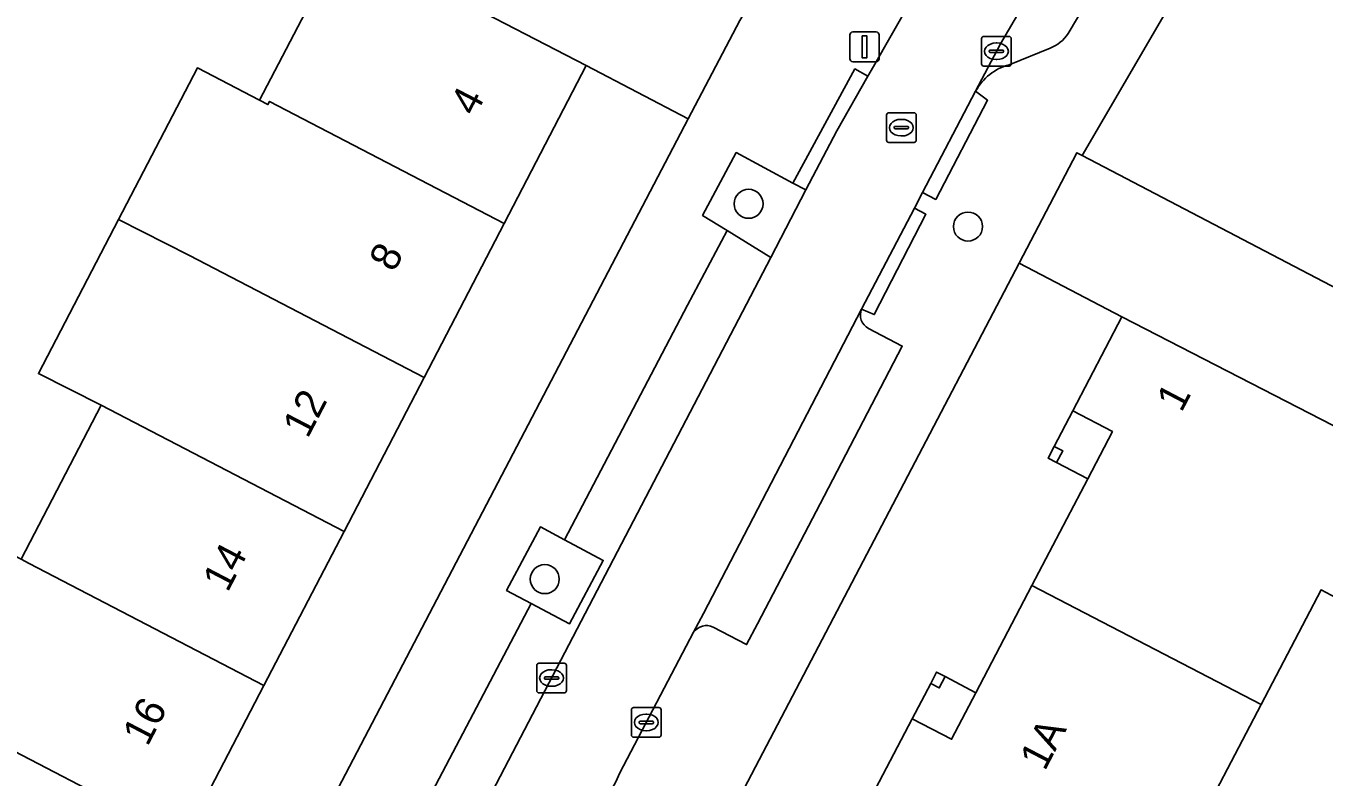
# Model space of a CAD drawing. Extents: x 160349 to 161355, y 381727 to 382854.
# Drawn here: x 160793.05 to 160836.79, y 382084.42 to 382109.72 of the extents above; entities that cross this region are included whole.
import ezdxf

# ---------------------------------------------------------------- set-up
doc = ezdxf.new("R2010")
doc.units = 0
for name, color, linetype in [('IMGEO_Boom', 7, 'Continuous'), ('IMGEO_Erf', 7, 'Continuous'), ('IMGEO_Groenvoorziening', 7, 'Continuous'), ('IMGEO_Kolk', 7, 'Continuous'), ('IMGEO_Lichtmast', 7, 'Continuous'), ('IMGEO_Muur', 7, 'Continuous'), ('IMGEO_Pand', 7, 'Continuous'), ('IMGEO_Pand_nummerreeks', 7, 'Continuous'), ('IMGEO_Pand_overbouw', 7, 'Continuous'), ('IMGEO_Parkeervlak_open', 7, 'Continuous'), ('IMGEO_Rijbaan_lokaal_open', 7, 'Continuous'), ('IMGEO_Rioolput', 7, 'Continuous'), ('IMGEO_Voetpad_halfverhard', 7, 'Continuous'), ('IMGEO_Voetpad_open', 7, 'Continuous')]:
    doc.layers.add(name, color=color, linetype=linetype)

msp = doc.modelspace()

# ---------------------------------------------------------------- linework, layer by layer
at = {"layer": 'IMGEO_Boom'}
for centre in [(160817.404, 382103.73), (160824.796, 382102.962), (160810.535, 382091.084)]:
    msp.add_circle(centre, 0.489, dxfattribs=at)
at = {"layer": 'IMGEO_Erf'}
for points in [[(160842.749, 382129.543), (160835.677, 382117.417), (160828.644, 382105.359), (160839.235, 382099.82)], [(160770.681, 382054.01), (160771.973, 382056.494), (160774.003, 382055.443), (160776.698, 382060.627), (160777.987, 382063.105), (160775.898, 382064.191), (160777.308, 382066.904), (160779.397, 382065.817), (160782.089, 382070.994), (160783.303, 382073.329), (160781.132, 382074.476), (160782.626, 382077.35), (160785.319, 382082.53), (160787.492, 382081.384), (160790.191, 382086.575), (160788.349, 382087.527), (160791.046, 382092.715), (160792.886, 382091.758), (160795.583, 382096.945), (160793.473, 382098.009), (160796.174, 382103.204), (160798.829, 382108.309), (160800.926, 382107.218), (160803.747, 382112.644)], [(160785.858, 382050.188), (160815.372, 382106.589), (160811.933, 382108.388), (160809.166, 382103.067), (160806.468, 382097.879), (160803.77, 382092.691), (160801.072, 382087.502), (160798.374, 382082.314), (160795.676, 382077.125), (160792.978, 382071.937), (160790.28, 382066.748), (160787.582, 382061.561), (160784.884, 382056.371), (160782.186, 382051.184)], [(160807.837, 382054.259), (160809.727, 382057.872), (160811.811, 382061.857), (160812.433, 382063.047), (160811.083, 382063.753), (160812.701, 382066.846), (160814.29, 382069.884), (160815.647, 382069.175), (160816.477, 382070.761), (160818.349, 382074.341), (160820.249, 382077.974), (160821.058, 382079.522), (160819.702, 382080.232), (160821.314, 382083.315), (160822.918, 382086.381), (160824.243, 382085.688), (160825.065, 382087.259), (160826.953, 382090.869), (160828.832, 382094.462), (160829.665, 382096.055), (160828.329, 382096.753), (160829.984, 382099.917), (160826.52, 382101.729), (160800.981, 382052.95)], [(160837.714, 382090.187), (160836.694, 382090.72), (160834.676, 382086.862), (160832.655, 382082.997), (160833.72, 382082.44), (160837.592, 382080.403), (160835.263, 382075.977), (160831.402, 382078.008), (160829.132, 382073.668), (160831.791, 382072.269), (160829.768, 382068.424), (160826.069, 382070.37), (160824.05, 382066.51), (160825.096, 382065.963), (160822.794, 382061.562), (160820.506, 382057.187), (160819.452, 382057.738), (160817.44, 382053.89)]]:
    msp.add_lwpolyline(points, dxfattribs=at)
for points in [[(160827.703, 382095.556), (160827.987, 382095.407), (160827.78, 382095.012), (160827.496, 382095.16)], [(160823.54, 382087.57), (160823.739, 382087.95), (160824.025, 382087.8), (160823.826, 382087.42)]]:
    msp.add_lwpolyline(points, close=True, dxfattribs=at)
at = {"layer": 'IMGEO_Groenvoorziening'}
for points in [[(160819.334, 382104.195), (160818.896, 382104.43), (160816.986, 382105.454), (160815.852, 382103.339), (160816.678, 382102.83), (160818.149, 382101.922)], [(160812.507, 382091.714), (160811.199, 382092.411), (160810.389, 382092.843), (160809.248, 382090.703), (160810.072, 382090.264), (160811.366, 382089.574)]]:
    msp.add_lwpolyline(points, close=True, dxfattribs=at)
at = {"layer": 'IMGEO_Kolk'}
for p, q in [((160825.255, 382108.442), (160825.255, 382109.294)), ((160825.33, 382109.368), (160826.182, 382109.368)), ((160825.743, 382109.148), (160825.768, 382109.148)), ((160826.256, 382109.294), (160826.256, 382108.442)), ((160825.514, 382108.862), (160825.514, 382108.874)), ((160825.952, 382108.825), (160825.554, 382108.825)), ((160825.557, 382108.911), (160825.955, 382108.911)), ((160825.998, 382108.874), (160825.998, 382108.862)), ((160826.182, 382108.368), (160825.33, 382108.368)), ((160825.766, 382108.588), (160825.741, 382108.588)), ((160810.262, 382087.327), (160810.262, 382088.179)), ((160810.337, 382088.253), (160811.189, 382088.253)), ((160811.263, 382088.179), (160811.263, 382087.327)), ((160810.521, 382087.747), (160810.521, 382087.759)), ((160810.959, 382087.71), (160810.561, 382087.71)), ((160810.564, 382087.796), (160810.962, 382087.796)), ((160810.75, 382088.033), (160810.775, 382088.033)), ((160811.005, 382087.759), (160811.005, 382087.747)), ((160811.189, 382087.253), (160810.337, 382087.253)), ((160810.773, 382087.473), (160810.748, 382087.473)), ((160813.455, 382085.831), (160813.455, 382086.683)), ((160813.53, 382086.757), (160814.382, 382086.757)), ((160813.943, 382086.537), (160813.968, 382086.537)), ((160814.456, 382086.683), (160814.456, 382085.831)), ((160813.714, 382086.251), (160813.714, 382086.263)), ((160814.152, 382086.214), (160813.754, 382086.214)), ((160813.757, 382086.3), (160814.155, 382086.3)), ((160813.966, 382085.977), (160813.941, 382085.977)), ((160814.198, 382086.263), (160814.198, 382086.251)), ((160814.382, 382085.757), (160813.53, 382085.757))]:
    msp.add_line(p, q, dxfattribs=at)
for points in [[(160825.255, 382108.442), (160825.255, 382109.294)], [(160825.33, 382109.368), (160826.182, 382109.368)], [(160826.256, 382109.294), (160826.256, 382108.442)], [(160826.182, 382108.368), (160825.33, 382108.368)], [(160810.262, 382087.327), (160810.262, 382088.179)], [(160810.337, 382088.253), (160811.189, 382088.253)], [(160811.263, 382088.179), (160811.263, 382087.327)], [(160811.189, 382087.253), (160810.337, 382087.253)], [(160813.455, 382085.831), (160813.455, 382086.683)], [(160813.53, 382086.757), (160814.382, 382086.757)], [(160814.456, 382086.683), (160814.456, 382085.831)], [(160814.382, 382085.757), (160813.53, 382085.757)]]:
    msp.add_lwpolyline(points, dxfattribs=at)
for centre, radius, start, end in [((160825.332, 382109.292), 0.0765, 91.552, 178.448), ((160825.332, 382109.292), 0.0765, 91.552, 178.448), ((160826.18, 382109.292), 0.0765, 1.552, 88.448), ((160826.18, 382109.292), 0.0765, 1.552, 88.448), ((160825.554, 382108.871), 0.0403, 85.8775, 175.7526), ((160825.551, 382108.861), 0.0366, 178.938, 274.7102), ((160825.955, 382108.868), 0.043, 264.8664, 352.4533), ((160825.959, 382108.873), 0.0386, 1.7309, 96.639), ((160825.332, 382108.444), 0.0765, 181.552, 268.448), ((160825.332, 382108.444), 0.0765, 181.552, 268.448), ((160826.18, 382108.444), 0.0765, 271.552, 358.448), ((160826.18, 382108.444), 0.0765, 271.552, 358.448), ((160810.339, 382088.177), 0.0765, 91.552, 178.448), ((160810.339, 382088.177), 0.0765, 91.552, 178.448), ((160811.187, 382088.177), 0.0765, 1.552, 88.448), ((160811.187, 382088.177), 0.0765, 1.552, 88.448), ((160810.561, 382087.756), 0.0403, 85.8775, 175.7526), ((160810.558, 382087.746), 0.0366, 178.938, 274.7102), ((160810.962, 382087.753), 0.043, 264.8664, 352.4533), ((160810.966, 382087.758), 0.0386, 1.7309, 96.639), ((160810.339, 382087.329), 0.0765, 181.552, 268.448), ((160810.339, 382087.329), 0.0765, 181.552, 268.448), ((160811.187, 382087.329), 0.0765, 271.552, 358.448), ((160811.187, 382087.329), 0.0765, 271.552, 358.448), ((160813.532, 382086.681), 0.0765, 91.552, 178.448), ((160813.532, 382086.681), 0.0765, 91.552, 178.448), ((160814.38, 382086.681), 0.0765, 1.552, 88.448), ((160814.38, 382086.681), 0.0765, 1.552, 88.448), ((160813.754, 382086.26), 0.0403, 85.8775, 175.7526), ((160813.751, 382086.25), 0.0366, 178.938, 274.7102), ((160814.155, 382086.257), 0.043, 264.8664, 352.4533), ((160814.159, 382086.262), 0.0386, 1.7309, 96.639), ((160813.532, 382085.833), 0.0765, 181.552, 268.448), ((160813.532, 382085.833), 0.0765, 181.552, 268.448), ((160814.38, 382085.833), 0.0765, 271.552, 358.448), ((160814.38, 382085.833), 0.0765, 271.552, 358.448)]:
    msp.add_arc(centre, radius, start, end, dxfattribs=at)
for centre, major_axis, ratio, start_param, end_param in [((160825.742, 382108.868), (-0.387, 0.002), 0.722429, 4.712389, 7.853982), ((160825.767, 382108.868), (-0.39, 0.002), 0.717154, 1.570796, 4.712389), ((160810.749, 382087.753), (-0.387, 0.002), 0.722429, 4.712389, 7.853982), ((160810.774, 382087.753), (-0.39, 0.002), 0.717154, 1.570796, 4.712389), ((160813.942, 382086.257), (-0.387, 0.002), 0.722429, 4.712389, 7.853982), ((160813.967, 382086.257), (-0.39, 0.002), 0.717154, 1.570796, 4.712389)]:
    msp.add_ellipse(centre, major_axis=major_axis, ratio=ratio, start_param=start_param, end_param=end_param, dxfattribs=at)
at = {"layer": 'IMGEO_Lichtmast'}
for p, q in [((160820.914, 382109.518), (160821.704, 382109.518)), ((160821.704, 382109.518), (160820.914, 382109.518)), ((160820.814, 382108.618), (160820.814, 382109.418)), ((160820.814, 382109.418), (160820.814, 382108.618)), ((160821.804, 382109.418), (160821.804, 382108.618)), ((160821.804, 382108.618), (160821.804, 382109.418)), ((160821.704, 382108.518), (160820.914, 382108.518)), ((160820.914, 382108.518), (160821.704, 382108.518))]:
    msp.add_line(p, q, dxfattribs=at)
msp.add_lwpolyline([(160821.234, 382109.393), (160821.384, 382109.393), (160821.384, 382108.643), (160821.234, 382108.643), (160821.234, 382109.393)], dxfattribs=at)
for centre, start, end in [((160820.914, 382109.418), 90, 180), ((160820.914, 382109.418), 90, 180), ((160821.704, 382109.418), 0, 90), ((160821.704, 382109.418), 360, 90), ((160820.914, 382108.618), 180, 270), ((160820.914, 382108.618), 180, 270), ((160821.704, 382108.618), 270, 0), ((160821.704, 382108.618), 270, 0)]:
    msp.add_arc(centre, 0.1, start, end, dxfattribs=at)
at = {"layer": 'IMGEO_Muur'}
msp.add_lwpolyline([(160828.644, 382105.359), (160835.677, 382117.417)], dxfattribs=at)
at = {"layer": 'IMGEO_Pand'}
for points in [[(160809.166, 382103.067), (160811.933, 382108.388), (160807.497, 382110.694), (160803.747, 382112.644), (160800.926, 382107.218), (160801.205, 382107.073), (160801.26, 382107.178)], [(160809.166, 382103.067), (160801.26, 382107.178), (160801.205, 382107.073), (160800.926, 382107.218), (160798.829, 382108.309), (160796.174, 382103.204), (160798.562, 382101.991), (160806.468, 382097.879)], [(160828.644, 382105.359), (160828.467, 382105.452), (160826.52, 382101.729), (160829.984, 382099.917), (160837.1, 382096.26), (160839.235, 382099.82)], [(160806.468, 382097.879), (160798.562, 382101.991), (160796.174, 382103.204), (160793.473, 382098.009), (160795.583, 382096.945), (160795.864, 382096.803), (160803.77, 382092.691)], [(160840.049, 382094.652), (160837.1, 382096.26), (160829.984, 382099.917), (160828.329, 382096.753), (160829.665, 382096.055), (160828.832, 382094.462), (160826.953, 382090.869), (160834.676, 382086.862), (160836.694, 382090.72), (160837.714, 382090.187)], [(160792.886, 382091.758), (160793.165, 382091.614), (160801.072, 382087.502), (160803.77, 382092.691), (160795.864, 382096.803), (160795.583, 382096.945)], [(160827.987, 382095.407), (160827.703, 382095.556), (160827.496, 382095.16), (160827.78, 382095.012)], [(160801.072, 382087.502), (160793.165, 382091.614), (160792.886, 382091.758), (160791.046, 382092.715), (160788.349, 382087.527), (160790.191, 382086.575), (160790.467, 382086.426), (160798.374, 382082.314)], [(160826.953, 382090.869), (160825.065, 382087.259), (160824.243, 382085.688), (160822.918, 382086.381), (160821.314, 382083.315), (160831.402, 382078.008), (160835.263, 382075.977), (160837.592, 382080.403), (160833.72, 382082.44), (160832.655, 382082.997), (160834.676, 382086.862)], [(160823.54, 382087.57), (160823.826, 382087.42), (160824.025, 382087.8), (160823.739, 382087.95)], [(160795.676, 382077.125), (160798.374, 382082.314), (160790.467, 382086.426), (160790.191, 382086.575), (160787.492, 382081.384), (160787.768, 382081.238)]]:
    msp.add_lwpolyline(points, close=True, dxfattribs=at)
at = {"layer": 'IMGEO_Pand_overbouw'}
for points in [[(160829.665, 382096.055), (160828.329, 382096.753), (160827.703, 382095.556), (160827.987, 382095.407), (160827.78, 382095.012), (160828.832, 382094.462)], [(160825.065, 382087.259), (160824.025, 382087.8), (160823.826, 382087.42), (160823.54, 382087.57), (160822.918, 382086.381), (160824.243, 382085.688)]]:
    msp.add_lwpolyline(points, close=True, dxfattribs=at)
at = {"layer": 'IMGEO_Parkeervlak_open'}
for points in [[(160830.73, 382117.391), (160825.888, 382109.122), (160825.053, 382107.525)], [(160828.175, 382109.465), (160830.969, 382114.176)], [(160826.185, 382108.417), (160827.56, 382108.973)], [(160821.211, 382100.185), (160815.882, 382089.93), (160815.548, 382089.292)], [(160822.583, 382098.937), (160821.446, 382099.527)], [(160816.208, 382089.468), (160817.337, 382088.882), (160817.7, 382089.575), (160819.954, 382093.882), (160822.583, 382098.937)]]:
    msp.add_lwpolyline(points, dxfattribs=at)
msp.add_lwpolyline([(160808.496, 382083.401), (160818.149, 382101.922), (160816.678, 382102.83), (160815.347, 382100.318), (160811.199, 382092.411), (160812.507, 382091.714), (160811.366, 382089.574), (160810.072, 382090.264), (160806.06, 382082.618), (160800.949, 382072.885), (160802.295, 382072.181), (160801.183, 382070.054), (160799.833, 382070.76), (160796.773, 382064.931), (160794.848, 382061.235), (160796.305, 382060.431), (160795.225, 382058.478), (160793.818, 382059.258), (160786.33, 382044.882), (160786.132, 382044.532), (160787.675, 382043.693), (160790.333, 382048.763), (160791.683, 382051.339), (160794.187, 382056.116)], close=True, dxfattribs=at)
for centre, radius, start, end in [((160827.1, 382110.179), 1.291, 290.8978, 326.4218), ((160826.68, 382106.624), 1.86, 105.446, 151.0292), ((160821.682, 382099.982), 0.513, 156.7068, 242.6008), ((160815.982, 382088.991), 0.528, 64.6138, 145.249)]:
    msp.add_arc(centre, radius, start, end, dxfattribs=at)
at = {"layer": 'IMGEO_Rijbaan_lokaal_open'}
for points in [[(160795.072, 382050.062), (160798.583, 382056.787), (160804.319, 382067.782), (160807.108, 382073.197), (160807.247, 382073.463), (160812.87, 382084.152), (160812.927, 382084.26), (160813.067, 382084.559), (160815.548, 382089.292), (160815.882, 382089.93), (160821.211, 382100.185), (160822.991, 382103.583), (160823.266, 382104.109), (160825.053, 382107.525), (160825.888, 382109.122), (160830.73, 382117.391)], [(160822.844, 382110.527), (160821.61, 382108.36), (160821.424, 382108.034), (160820.371, 382106.185), (160819.334, 382104.195), (160818.149, 382101.922), (160808.496, 382083.401), (160794.187, 382056.116), (160791.683, 382051.339)]]:
    msp.add_lwpolyline(points, dxfattribs=at)
at = {"layer": 'IMGEO_Rioolput'}
for p, q in [((160822.05, 382105.869), (160822.05, 382106.721)), ((160822.125, 382106.795), (160822.977, 382106.795)), ((160822.538, 382106.575), (160822.563, 382106.575)), ((160823.051, 382106.721), (160823.051, 382105.869)), ((160822.309, 382106.289), (160822.309, 382106.301)), ((160822.747, 382106.252), (160822.349, 382106.252)), ((160822.352, 382106.338), (160822.75, 382106.338)), ((160822.561, 382106.015), (160822.536, 382106.015)), ((160822.793, 382106.301), (160822.793, 382106.289)), ((160822.977, 382105.795), (160822.125, 382105.795))]:
    msp.add_line(p, q, dxfattribs=at)
for points in [[(160822.05, 382105.869), (160822.05, 382106.721)], [(160822.125, 382106.795), (160822.977, 382106.795)], [(160823.051, 382106.721), (160823.051, 382105.869)], [(160822.977, 382105.795), (160822.125, 382105.795)]]:
    msp.add_lwpolyline(points, dxfattribs=at)
for centre, radius, start, end in [((160822.127, 382106.719), 0.0765, 91.552, 178.448), ((160822.127, 382106.719), 0.0765, 91.552, 178.448), ((160822.975, 382106.719), 0.0765, 1.552, 88.448), ((160822.975, 382106.719), 0.0765, 1.552, 88.448), ((160822.349, 382106.298), 0.0403, 85.8775, 175.7526), ((160822.346, 382106.288), 0.0366, 178.938, 274.7102), ((160822.75, 382106.295), 0.043, 264.8664, 352.4533), ((160822.754, 382106.3), 0.0386, 1.7309, 96.639), ((160822.127, 382105.871), 0.0765, 181.552, 268.448), ((160822.127, 382105.871), 0.0765, 181.552, 268.448), ((160822.975, 382105.871), 0.0765, 271.552, 358.448), ((160822.975, 382105.871), 0.0765, 271.552, 358.448)]:
    msp.add_arc(centre, radius, start, end, dxfattribs=at)
for centre, major_axis, ratio, start_param, end_param in [((160822.537, 382106.295), (-0.387, 0.002), 0.722429, 4.712389, 7.853982), ((160822.562, 382106.295), (-0.39, 0.002), 0.717154, 1.570796, 4.712389)]:
    msp.add_ellipse(centre, major_axis=major_axis, ratio=ratio, start_param=start_param, end_param=end_param, dxfattribs=at)
at = {"layer": 'IMGEO_Voetpad_halfverhard'}
msp.add_lwpolyline([(160807.497, 382110.694), (160811.933, 382108.388), (160815.372, 382106.589), (160817.107, 382109.905)], dxfattribs=at)
at = {"layer": 'IMGEO_Voetpad_open'}
for points in [[(160830.101, 382132.01), (160817.137, 382109.957), (160817.107, 382109.905), (160815.372, 382106.589), (160785.858, 382050.188), (160759.835, 382000), (160751.631, 381984.178), (160750, 381983.553), (160754.728, 381981.086)], [(160826.52, 382101.729), (160828.467, 382105.452), (160828.644, 382105.359), (160835.677, 382117.417), (160842.749, 382129.543), (160839.149, 382131.333)], [(160830.969, 382114.176), (160828.175, 382109.465)], [(160786.33, 382044.882), (160793.818, 382059.258), (160793.126, 382059.641), (160794.204, 382061.59), (160794.848, 382061.235), (160796.773, 382064.931), (160799.833, 382070.76), (160799.056, 382071.166), (160800.168, 382073.293), (160800.949, 382072.885), (160806.06, 382082.618), (160810.072, 382090.264), (160809.248, 382090.703), (160810.389, 382092.843), (160811.199, 382092.411), (160815.347, 382100.318), (160816.678, 382102.83), (160815.852, 382103.339), (160816.986, 382105.454), (160818.896, 382104.43), (160820.985, 382108.272), (160821.424, 382108.034), (160821.61, 382108.36), (160822.844, 382110.527)], [(160827.56, 382108.973), (160826.185, 382108.417)], [(160825.053, 382107.525), (160825.456, 382107.217), (160823.709, 382103.877), (160823.266, 382104.109), (160822.991, 382103.583), (160823.38, 382103.379), (160821.639, 382100), (160821.211, 382100.185)], [(160758.807, 381979.11), (160762.776, 381976.768), (160762.232, 381978.206), (160773.531, 382000), (160800.003, 382051.064), (160800.514, 382052.05), (160800.981, 382052.95), (160826.52, 382101.729)], [(160821.446, 382099.527), (160822.583, 382098.937), (160819.954, 382093.882), (160817.7, 382089.575), (160817.337, 382088.882), (160816.208, 382089.468)], [(160815.548, 382089.292), (160813.067, 382084.559), (160812.927, 382084.26), (160812.87, 382084.152)]]:
    msp.add_lwpolyline(points, dxfattribs=at)
for points in [[(160820.371, 382106.185), (160821.424, 382108.034), (160820.985, 382108.272), (160818.896, 382104.43), (160819.334, 382104.195)], [(160825.053, 382107.525), (160823.266, 382104.109), (160823.709, 382103.877), (160825.456, 382107.217)], [(160822.991, 382103.583), (160821.211, 382100.185), (160821.639, 382100), (160823.38, 382103.379)]]:
    msp.add_lwpolyline(points, close=True, dxfattribs=at)
for centre, radius, start, end in [((160827.1, 382110.179), 1.291, 290.8978, 326.4218), ((160826.68, 382106.624), 1.86, 105.446, 151.0292), ((160821.682, 382099.982), 0.513, 156.7068, 242.6008), ((160815.982, 382088.991), 0.528, 64.6138, 145.249)]:
    msp.add_arc(centre, radius, start, end, dxfattribs=at)

# ---------------------------------------------------------------- texts
at = {"layer": 'IMGEO_Pand_nummerreeks'}
for s, rotation, p in [('4', 62.5249, (160808.187, 382106.645)), ('8', 62.5249, (160805.456, 382101.395)), ('12', 62.5235, (160802.543, 382095.792)), ('1', 62.3894, (160831.989, 382096.672)), ('14', 62.528, (160799.847, 382090.609)), ('16', 62.5269, (160797.148, 382085.418)), ('1A', 62.4973, (160827.383, 382084.591))]:
    msp.add_text(s, height=1, rotation=rotation, dxfattribs=at).set_placement(p)

doc.saveas('drawing.dxf')
